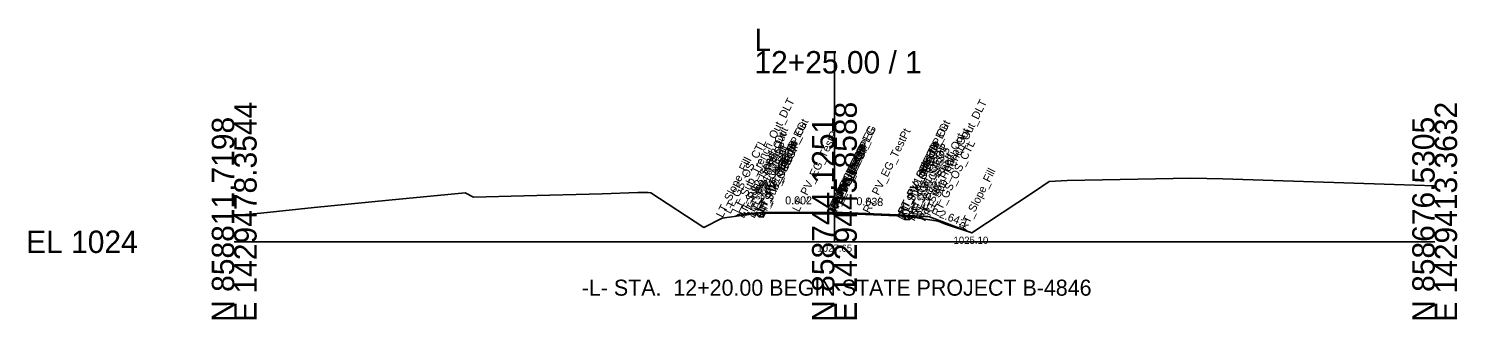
# Model space of a CAD drawing. Extents: x -26 to 153, y -10 to 13058.
# Drawn here: x -25.7 to 152.8, y 1490.3 to 1526.6 of the extents above; entities that cross this region are included whole.
import ezdxf

# ---------------------------------------------------------------- set-up
doc = ezdxf.new("R2010")
doc.units = 0
for name, color, linetype in [('Default', 7, 'Continuous'), ('Exist Cross Section Cell', 7, 'Continuous'), ('Exist XS Center Line Elevation Label', 7, 'Continuous'), ('Exist XS Ground Line', 7, 'Continuous'), ('Prop CMT Pvmt Course 1', 7, 'Continuous'), ('Prop CMT Pvmt Surface', 7, 'Continuous'), ('Prop CMT Pvmt Surface Shoulder', 7, 'Continuous'), ('Prop CMT Pvmt Wedge Surface 1', 7, 'Continuous'), ('Prop CMT Shld Paved Course 1', 7, 'Continuous'), ('Prop CMT Slope Grass', 7, 'Continuous'), ('Prop CMT Subgrade Earthwork', 7, 'Continuous'), ('Prop XS Dump Level', 7, 'Continuous'), ('Prop XS SE Text', 7, 'Continuous'), ('Prop XS Side Slope Text', 7, 'Continuous'), ('Prop XSC Text', 7, 'Continuous')]:
    doc.layers.add(name, color=color, linetype=linetype)

msp = doc.modelspace()

# ---------------------------------------------------------------- linework, layer by layer
at = {"layer": 'Exist Cross Section Cell'}
for p, q in [((75, 1500), (75, 1523.82)), ((0, 1500), (75, 1500)), ((75, 1500), (150, 1500))]:
    msp.add_line(p, q, dxfattribs=at)
at = {"layer": 'Exist XS Ground Line'}
msp.add_lwpolyline([(0, 1503.29), (3.32, 1503.57), (9.98, 1504.29), (19.3, 1505.18), (28.85, 1506.1), (29.89, 1505.58), (36.2, 1505.74), (45.97, 1505.99), (50.43, 1506.16), (51.72, 1506.15), (52.07, 1506.13), (58.69, 1501.79), (60.95, 1502.93), (63.06, 1503.23), (66.11, 1503.67), (72.62, 1503.66), (75.1, 1503.65), (81.49, 1503.39), (83.76, 1503.3), (85.55, 1502.96), (87.94, 1502.56), (88.86, 1502.21), (92.16, 1501.1), (99.87, 1506.19), (101.83, 1507.51), (104.08, 1507.64), (119.53, 1507.94), (123.54, 1507.86), (144.94, 1507.17), (150, 1506.99)], dxfattribs=at)
at = {"layer": 'Prop CMT Pvmt Course 1'}
for points in [[(75, 1503.68), (66.13, 1503.67)], [(66.13, 1503.67), (66.13, 1503.12), (66.13, 1503.12), (66.13, 1503.54)], [(66.13, 1503.54), (75, 1503.56)], [(75, 1503.14), (75, 1503.68)], [(75, 1503.68), (83.88, 1503.34)], [(75, 1503.14), (75, 1503.68)], [(75, 1503.56), (75, 1503.14), (75, 1503.14)], [(83.76, 1503.22), (75, 1503.56)], [(75, 1503.56), (75, 1503.14), (75, 1503.14)], [(83.88, 1503.34), (83.88, 1502.8)], [(83.76, 1502.81), (83.76, 1503.22)], [(83.88, 1502.8), (83.76, 1502.81)]]:
    msp.add_lwpolyline(points, dxfattribs=at)
at = {"layer": 'Prop CMT Pvmt Surface'}
for points in [[(75, 1503.68), (66.13, 1503.67)], [(75, 1503.68), (83.88, 1503.34)]]:
    msp.add_lwpolyline(points, dxfattribs=at)
at = {"layer": 'Prop CMT Pvmt Surface Shoulder'}
for points in [[(66.13, 1503.67), (66.13, 1503.67)], [(83.88, 1503.34), (83.88, 1503.34)]]:
    msp.add_lwpolyline(points, dxfattribs=at)
at = {"layer": 'Prop CMT Pvmt Wedge Surface 1'}
for points in [[(66.13, 1503.12), (66.13, 1503.67)], [(75, 1503.56), (66.13, 1503.54)], [(66.13, 1503.54), (66.13, 1503.12), (66.13, 1503.12)], [(75, 1503.56), (83.76, 1503.22)], [(83.88, 1502.8), (83.88, 1503.34)], [(83.76, 1503.22), (83.76, 1502.81)], [(83.76, 1502.81), (83.88, 1502.8)]]:
    msp.add_lwpolyline(points, dxfattribs=at)
at = {"layer": 'Prop CMT Shld Paved Course 1'}
for points in [[(66.13, 1503.67), (65.57, 1503.11)], [(66.13, 1503.67), (66.13, 1503.67)], [(66.13, 1503.12), (66.13, 1503.67)], [(83.88, 1503.34), (83.88, 1503.34)], [(83.88, 1503.34), (84.43, 1502.79)], [(83.88, 1502.8), (83.88, 1503.34)], [(65.57, 1503.11), (66.13, 1503.12)], [(84.43, 1502.79), (83.88, 1502.8)]]:
    msp.add_lwpolyline(points, dxfattribs=at)
at = {"layer": 'Prop CMT Slope Grass'}
for points in [[(66.13, 1503.67), (63.13, 1503.43), (62.6, 1503.16)], [(83.88, 1503.34), (86.88, 1503.1), (92.16, 1501.1)]]:
    msp.add_lwpolyline(points, dxfattribs=at)
at = {"layer": 'Prop CMT Subgrade Earthwork'}
for points in [[(65.57, 1503.11), (65.1, 1503.58)], [(66.13, 1503.12), (66.14, 1503.67)], [(83.76, 1502.81), (83.75, 1503.3)], [(84.43, 1502.79), (84.9, 1503.26)], [(66.13, 1503.12), (65.57, 1503.11)], [(66.13, 1503.12), (66.13, 1503.12)], [(83.76, 1502.81), (83.88, 1502.8)], [(83.88, 1502.8), (84.43, 1502.79)]]:
    msp.add_lwpolyline(points, dxfattribs=at)

# ---------------------------------------------------------------- texts
at = {"layer": 'Default'}
for s, height, p in [('-', 0.0001, (0, 1500)), ('1025.10', 0.9, (89.87, 1499.74))]:
    msp.add_text(s, height=height, dxfattribs=at).set_placement(p)
at = {"layer": 'Exist Cross Section Cell'}
for s, p in [('L', (65, 1523.82)), ('12+25.00 / 1', (65, 1521.02)), ('EL 1024', (-26, 1498.6))]:
    msp.add_text(s, height=2.8, dxfattribs=at).set_placement(p)
for s, p in [('E 1429478.3544', (2.8, 1490)), ('E 1429445.8588', (77.8, 1490)), ('E 1429413.3632', (152.8, 1490)), ('N 858811.7198', (0, 1490)), ('N 858744.1251', (75, 1490)), ('N 858676.5305', (150, 1490))]:
    msp.add_text(s, height=2.8, rotation=90, dxfattribs=at).set_placement(p)
at = {"layer": 'Exist XS Center Line Elevation Label'}
msp.add_text('1027.65', height=0.9, dxfattribs=at).set_placement((72.86, 1498.75))
msp.add_text('1027.65', height=0.9, dxfattribs=at).set_placement((72.86, 1498.75))
msp.add_text('1027.65', height=0.9, dxfattribs=at).set_placement((72.86, 1498.75))
at = {"layer": 'Prop XS Dump Level'}
for s, p in [('LT_Sub_Trench_Out_DLT', (63.03, 1503.51)), ('RT_Sub_Trench_Out_DLT', (86.97, 1503.14)), ('LT_Sub_Trench_Out', (63.69, 1502.85)), ('LT_PV_OEEOP_EG', (66.11, 1503.67)), ('LT_PV_Sub_Tie_Out', (66.13, 1503.67)), ('LT_PV_EG_TestPt', (70.56, 1503.66)), ('RT_PV_IEEOP_EG', (75, 1503.65)), ('LT_PV_IEEOP_EG', (75, 1503.65)), ('RT_PV_EG_TestPt', (79.38, 1503.47)), ('RT_PV_Sub_Tie_Out', (83.75, 1503.3)), ('RT_PV_OEEOP_EG', (83.76, 1503.3)), ('RT_Sub_Trench_Out', (86.31, 1502.48)), ('LT_GS_OS_CTL', (62, 1503.42)), ('LT_PS2_Shelf_Out', (63.95, 1503.1)), ('LT_PV1_OEOT', (65, 1503.66)), ('LT_PS1_OEOP', (65, 1503.66)), ('LT_PV1_OEEOP', (66.11, 1503.54)), ('LT_PV2_OEEOP', (66.11, 1503.12)), ('LT_Sub_OEEOP', (66.11, 1502.87)), ('RT_PV1_IEEOP', (75, 1503.56)), ('LT_PV1_IEEOP', (75, 1503.56)), ('RT_PV2_IEEOP', (75, 1503.14)), ('RT_PV1_OEEOP', (83.76, 1503.22)), ('RT_PV2_OEEOP', (83.76, 1502.81)), ('RT_Sub_OEEOP', (83.76, 1502.56)), ('RT_PV1_OEOT', (85, 1503.3)), ('RT_PS1_OEOP', (85, 1503.3)), ('RT_PS2_Shelf_Out', (86.05, 1502.74)), ('RT_GS_OS_CTL', (88, 1503.06)), ('LT_Slope_Fill', (61.03, 1502.94)), ('LT_PS2_OEOP', (64.45, 1503.11)), ('LT_PV2_OEOT', (65, 1503.12)), ('LT_Sub_OEOT', (65, 1502.87)), ('LT_PV2_IEEOP', (75, 1503.14)), ('RT_PV2_OEOT', (85, 1502.76)), ('RT_Sub_OEOT', (85, 1502.51)), ('RT_PS2_OEOP', (85.55, 1502.75)), ('PV1_PGL', (75, 1503.68)), ('RT_Slope_Fill', (91.42, 1501.35)), ('PV2_PGL', (75, 1503.14))]:
    msp.add_text(s, height=1, rotation=63.5833, dxfattribs=at).set_placement(p)
at = {"layer": 'Prop XS SE Text'}
for s, rotation, p in [('0.002', 0.0917, (68.85, 1504.67)), ('0.038', 357.8238, (77.73, 1504.58))]:
    msp.add_text(s, height=1, rotation=rotation, dxfattribs=at).set_placement(p)
at = {"layer": 'Prop XS Side Slope Text'}
msp.add_text('2.64:1', height=1, rotation=339.2636, dxfattribs=at).set_placement((88.01, 1503.08))
at = {"layer": 'Prop XSC Text'}
msp.add_text('-L- STA.  12+20.00 BEGIN STATE PROJECT B-4846', height=2, dxfattribs=at).set_placement((43.43, 1493.27))

doc.saveas('drawing.dxf')
